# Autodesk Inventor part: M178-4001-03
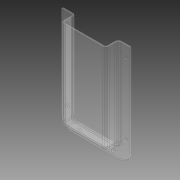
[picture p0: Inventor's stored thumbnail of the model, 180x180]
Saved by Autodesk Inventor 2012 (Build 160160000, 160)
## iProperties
Created: 2004-11
Part Number: M178-4001-03
Material: Plastic, Clear
Document SubType Name: Modeling
Designer: Autodesk, Inc.
Manufacturer: Standard
Standards Organization: Custom
Description: TOOL CADDY, PLASTIC, 2 x 4 x 0.625
Mass: 26.1813 g
Surface Area: 237.698 cm^2
Volume: 21.8178 cm^3
Density: 1.2 g/cm^3
CAGE: 1LJX3
Dept. ID: Product Design
Description #2: ---
Finish #1: ---
Finish #2: ---
Material ID: ---
Project Number: ---
Author: Autodesk, Inc.
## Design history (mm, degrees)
sketch "Sketch1"
  geometry: L1 (-25.4, 50.8)-(25.4, 50.8); L2 (25.4, 50.8)-(25.4, -50.8); L3 (25.4, -50.8)-(-25.4, -50.8); L4 (-25.4, -50.8)-(-25.4, 50.8); 3 further points
  constraints: 8 end point, 2 midpoint, 2 parallel, 1 horizontal, 1 horizontal alignment, 1 perpendicular, 1 vertical alignment
  dimensions: "Width" = 50.8 distance of L2.end L3.end; "Height" = 101.6 distance of L3.end L1.start
extrude "Extrusion1" new body sketch "Sketch1" taper "d3" = 0 deg; distance "Depth" = 15.875
shell "Shell1" dims "d4" = 1.905
sketch "Sketch2"
  geometry: L1 (-25.4, 50.8)-(-25.4, -50.8) reference; L2 (25.4, -50.8)-(25.4, 50.8) reference; L3 (-25.4, -50.8)-(25.4, -50.8) reference; L4 (25.4, 50.8)-(38.1, 50.8); L5 (38.1, 50.8)-(38.1, -51.435); L6 (26.035, -63.5)-(-26.035, -63.5); L7 (-38.1, -51.435)-(-38.1, 50.8); L8 (-38.1, 50.8)-(-25.4, 50.8); A1 r 12.065 centre (26.035, -51.435) between (26.035, -63.5) and (38.1, -51.435); A2 r 12.065 centre (-26.035, -51.435) between (-38.1, -51.435) and (-26.035, -63.5)
  constraints: 10 end point, 4 point on circle, 4 tangent, 3 parallel, 2 centre point, 2 collinear, 1 equal radius, 1 perpendicular
  dimensions: "d5" = 12.7 distance of L7.end L1.start; "d6" = 12.7 distance between parallel lines of L3 L6; "d7" = 12.065 radius of A2
extrude "Extrusion2" join sketch "Sketch2" distance "d8" = 1.905; taper "d9" = 0 deg
fillet "Fillet1" dims "d10" = 1.905, "d11" = 3.81
sketch "Sketch3"
  geometry: L1 (-27.305, 50.8)-(-38.1, 50.8) reference; L2 (-38.1, -51.435)-(-38.1, 50.8) reference; L3 (26.035, -63.5)-(-26.035, -63.5) reference; L4 (0, -63.5)-(0, -52.705); L5 (-21.59, -52.705)-(21.59, -52.705) reference; L6 (0, -89.358)-(0, 74.16) reference; A1 r 12.065 centre (-26.035, -51.435) between (-38.1, -51.435) and (-26.035, -63.5) reference; 9 further points
  constraints: 5 midpoint, 3 symmetric about line, 2 end point, 2 vertical alignment, 1 horizontal alignment, 1 perpendicular
  dimensions: "d13" = 19.05 distance from line of point (-19.05, -58.102) L2; "d14" = 22.225 distance from line of point (-32.702, -41.275) L3; "d15" = 12.7 distance from line of point (-32.702, 38.1) L1
hole "Hole1" sketch "Sketch3" at (-32.702, 38.1), (-32.702, -41.275), (-19.05, -58.102), (32.702, 38.1), (32.702, -41.275), (19.05, -58.102) diameter "d16" = 3.175; stored, may be unused: countersink angle "d20" = 82 deg, drill point angle "d22" = 118 deg; dims "d17" = 12.7, "d18" = 5.715, "d19" = 6.35, "d21" = 19.05
body "Solid1"
